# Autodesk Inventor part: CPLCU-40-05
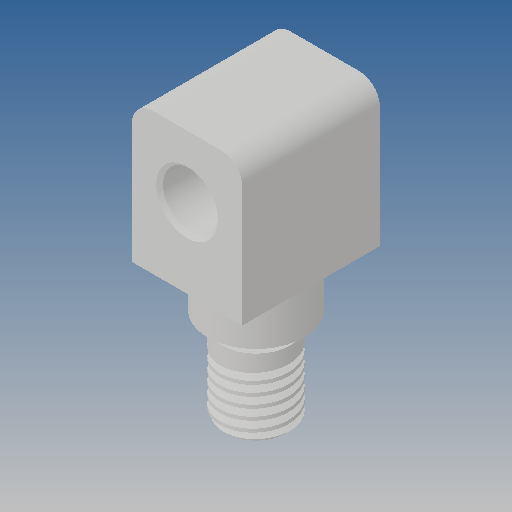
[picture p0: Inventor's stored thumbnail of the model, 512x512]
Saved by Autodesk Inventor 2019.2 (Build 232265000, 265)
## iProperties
Created: 2010-03
Part Number: CPLCU-40-05
Material: Ogólny
Document SubType Name: Modeling
Designer: CADENGINEERING4
Density: 1 g/cm^3
Appearance: Domyślna
Author: CADENGINEERING4
Revision Number: 1LAST_VERSION
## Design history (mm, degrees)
feature "Baza1"
node "Bryła1"
